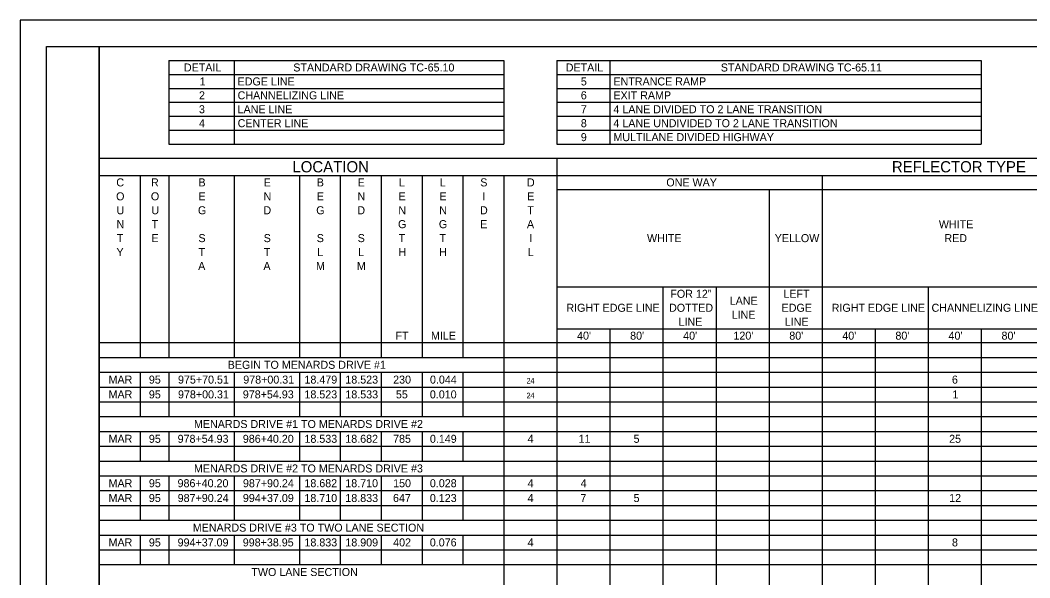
# Model space of a CAD drawing. Extents: x 0 to 34, y 0 to 22.
# Drawn here: x 0 to 19.14, y 11.44 to 22 of the extents above; entities that cross this region are included whole.
import ezdxf

# ---------------------------------------------------------------- set-up
doc = ezdxf.new("R2010")
doc.units = 0
for name, color, linetype in [('SH_Border', 7, 'Continuous'), ('SH_Cut_Line', 7, 'Continuous'), ('SH_Text', 7, 'Continuous')]:
    doc.layers.add(name, color=color, linetype=linetype)

msp = doc.modelspace()

# ---------------------------------------------------------------- linework, layer by layer
at = {"layer": 'SH_Border'}
for points in [[(0.5, 21.5), (1.5, 21.5), (1.5, 0.5), (0.5, 0.5)], [(1.5, 21.5), (33.5, 21.5), (33.5, 0.5), (1.5, 0.5)]]:
    msp.add_lwpolyline(points, close=True, dxfattribs=at)
at = {"layer": 'SH_Cut_Line'}
msp.add_lwpolyline([(0, 0), (34, 0), (34, 22), (0, 22)], close=True, dxfattribs=at)
at = {"layer": 'SH_Text'}
for p, q in [((2.819, 21.237), (9.166, 21.237)), ((2.819, 21.237), (2.819, 19.654)), ((4.055, 21.237), (4.055, 19.654)), ((9.166, 21.237), (9.166, 19.654)), ((10.172, 21.237), (18.217, 21.237)), ((10.172, 21.237), (10.172, 19.654)), ((11.178, 21.237), (11.178, 19.654)), ((18.217, 21.237), (18.217, 19.654)), ((2.819, 20.973), (9.166, 20.973)), ((10.172, 20.973), (18.217, 20.973)), ((2.819, 20.709), (9.166, 20.709)), ((10.172, 20.709), (18.217, 20.709)), ((2.819, 20.446), (9.166, 20.446)), ((10.172, 20.446), (18.217, 20.446)), ((2.819, 20.182), (9.166, 20.182)), ((10.172, 20.182), (18.217, 20.182)), ((2.819, 19.918), (9.166, 19.918)), ((10.172, 19.918), (18.217, 19.918)), ((2.819, 19.654), (9.166, 19.654)), ((10.172, 19.654), (18.217, 19.654)), ((1.5, 19.39), (32, 19.39)), ((1.5, 19.39), (1.5, 0.48)), ((10.172, 19.39), (10.172, 0.761)), ((1.5, 19.061), (32, 19.061)), ((2.275, 19.061), (2.275, 15.615)), ((2.819, 19.061), (2.819, 15.615)), ((4.055, 19.061), (4.055, 15.615)), ((5.292, 19.061), (5.292, 15.615)), ((6.067, 19.061), (6.067, 15.615)), ((6.842, 19.061), (6.842, 15.615)), ((7.616, 19.061), (7.616, 15.615)), ((8.391, 19.061), (8.391, 15.615)), ((9.166, 19.061), (9.166, 0.761)), ((15.2, 19.061), (15.2, 0.761)), ((10.172, 18.797), (25.257, 18.797)), ((14.195, 18.797), (14.195, 0.761)), ((10.172, 16.95), (25.257, 16.95)), ((12.183, 16.95), (12.183, 0.761)), ((13.189, 16.95), (13.189, 0.761)), ((17.212, 16.95), (17.212, 0.761)), ((10.172, 16.159), (26.807, 16.159)), ((11.178, 16.159), (11.178, 0.761)), ((16.206, 16.159), (16.206, 0.761)), ((18.217, 16.159), (18.217, 0.761)), ((1.5, 15.895), (32, 15.895)), ((1.5, 15.615), (32, 15.615)), ((1.5, 15.335), (32, 15.335)), ((2.275, 15.335), (2.275, 14.494)), ((2.819, 15.335), (2.819, 14.494)), ((4.055, 15.335), (4.055, 14.494)), ((5.292, 15.335), (5.292, 14.494)), ((6.067, 15.335), (6.067, 14.494)), ((6.842, 15.335), (6.842, 14.494)), ((7.616, 15.335), (7.616, 14.494)), ((8.391, 15.335), (8.391, 14.494)), ((1.5, 15.054), (32, 15.054)), ((1.5, 14.774), (32, 14.774)), ((1.5, 14.494), (32, 14.494)), ((1.5, 14.214), (32, 14.214)), ((2.275, 14.214), (2.275, 13.653)), ((2.819, 14.214), (2.819, 13.653)), ((4.055, 14.214), (4.055, 13.653)), ((5.292, 14.214), (5.292, 13.653)), ((6.067, 14.214), (6.067, 13.653)), ((6.842, 14.214), (6.842, 13.653)), ((7.616, 14.214), (7.616, 13.653)), ((8.391, 14.214), (8.391, 13.653)), ((1.5, 13.933), (32, 13.933)), ((1.5, 13.653), (32, 13.653)), ((1.5, 13.373), (32, 13.373)), ((2.275, 13.373), (2.275, 12.532)), ((2.819, 13.373), (2.819, 12.532)), ((4.055, 13.373), (4.055, 12.532)), ((5.292, 13.373), (5.292, 12.532)), ((6.067, 13.373), (6.067, 12.532)), ((6.842, 13.373), (6.842, 12.532)), ((7.616, 13.373), (7.616, 12.532)), ((8.391, 13.373), (8.391, 12.532)), ((1.5, 13.093), (32, 13.093)), ((1.5, 12.812), (32, 12.812)), ((1.5, 12.532), (32, 12.532)), ((1.5, 12.252), (32, 12.252)), ((2.275, 12.252), (2.275, 11.691)), ((2.819, 12.252), (2.819, 11.691)), ((4.055, 12.252), (4.055, 11.691)), ((5.292, 12.252), (5.292, 11.691)), ((6.067, 12.252), (6.067, 11.691)), ((6.842, 12.252), (6.842, 11.691)), ((7.616, 12.252), (7.616, 11.691)), ((8.391, 12.252), (8.391, 11.691)), ((1.5, 11.972), (32, 11.972)), ((1.5, 11.691), (32, 11.691))]:
    msp.add_line(p, q, dxfattribs=at)

# ---------------------------------------------------------------- texts
for s, height, p in [('DETAIL', 0.1517, (3.103, 21.029)), ('STANDARD DRAWING TC-65.10', 0.15168, (5.176, 21.029)), ('DETAIL', 0.1517, (10.34, 21.029)), ('STANDARD DRAWING TC-65.11', 0.15168, (13.279, 21.029)), ('1', 0.152, (3.402, 20.765)), ('EDGE LINE', 0.1517, (4.121, 20.765)), ('5', 0.152, (10.626, 20.765)), ('ENTRANCE RAMP', 0.15168, (11.244, 20.765)), ('2', 0.152, (3.389, 20.502)), ('CHANNELIZING LINE', 0.15168, (4.121, 20.502)), ('6', 0.152, (10.626, 20.502)), ('EXIT RAMP', 0.1517, (11.244, 20.502)), ('3', 0.152, (3.388, 20.238)), ('LANE LINE', 0.1517, (4.121, 20.238)), ('7', 0.152, (10.626, 20.238)), ('4 LANE DIVIDED TO 2 LANE TRANSITION', 0.15168, (11.244, 20.238)), ('4', 0.152, (3.389, 19.974)), ('CENTER LINE', 0.15168, (4.121, 19.974)), ('8', 0.152, (10.626, 19.974)), ('4 LANE UNDIVIDED TO 2 LANE TRANSITION', 0.15168, (11.244, 19.974)), ('9', 0.152, (10.626, 19.71)), ('MULTILANE DIVIDED HIGHWAY', 0.15168, (11.244, 19.71)), ('LOCATION', 0.2123, (5.159, 19.119)), ('REFLECTOR TYPE', 0.21235, (16.522, 19.119)), ('C', 0.152, (1.822, 18.853)), ('R', 0.152, (2.479, 18.853)), ('B', 0.152, (3.379, 18.853)), ('E', 0.152, (4.615, 18.853)), ('B', 0.152, (5.621, 18.853)), ('E', 0.152, (6.396, 18.853)), ('L', 0.152, (7.179, 18.853)), ('L', 0.152, (7.954, 18.853)), ('S', 0.152, (8.72, 18.853)), ('D', 0.152, (9.605, 18.853)), ('ONE WAY', 0.1517, (12.247, 18.853)), ('O', 0.152, (1.818, 18.589)), ('O', 0.152, (2.477, 18.589)), ('E', 0.152, (3.379, 18.589)), ('N', 0.152, (4.613, 18.589)), ('E', 0.152, (5.621, 18.589)), ('N', 0.152, (6.393, 18.589)), ('E', 0.152, (7.171, 18.589)), ('E', 0.152, (7.945, 18.589)), ('I', 0.152, (8.761, 18.589)), ('E', 0.152, (9.611, 18.589)), ('U', 0.152, (1.826, 18.325)), ('U', 0.152, (2.486, 18.325)), ('G', 0.152, (3.369, 18.325)), ('D', 0.152, (4.61, 18.325)), ('G', 0.152, (5.611, 18.325)), ('D', 0.152, (6.39, 18.325)), ('N', 0.152, (7.168, 18.325)), ('N', 0.152, (7.943, 18.325)), ('D', 0.152, (8.715, 18.325)), ('T', 0.152, (9.613, 18.325)), ('N', 0.152, (1.826, 18.062)), ('T', 0.152, (2.491, 18.062)), ('G', 0.152, (7.161, 18.062)), ('G', 0.152, (7.936, 18.062)), ('E', 0.152, (8.72, 18.062)), ('A', 0.152, (9.605, 18.062)), ('WHITE', 0.1517, (17.412, 18.062)), ('T', 0.152, (1.831, 17.798)), ('E', 0.152, (2.488, 17.798)), ('S', 0.152, (3.379, 17.798)), ('S', 0.152, (4.615, 17.798)), ('S', 0.152, (5.621, 17.798)), ('S', 0.152, (6.396, 17.798)), ('T', 0.152, (7.173, 17.798)), ('T', 0.152, (7.948, 17.798)), ('I', 0.152, (9.651, 17.798)), ('WHITE', 0.1517, (11.881, 17.798)), ('YELLOW', 0.1517, (14.301, 17.798)), ('RED', 0.1517, (17.518, 17.798)), ('Y', 0.152, (1.825, 17.534)), ('T', 0.152, (3.381, 17.534)), ('T', 0.152, (4.617, 17.534)), ('L', 0.152, (5.63, 17.534)), ('L', 0.152, (6.405, 17.534)), ('H', 0.152, (7.168, 17.534)), ('H', 0.152, (7.943, 17.534)), ('L', 0.152, (9.619, 17.534)), ('A', 0.152, (3.373, 17.27)), ('A', 0.152, (4.61, 17.27)), ('M', 0.152, (5.607, 17.27)), ('M', 0.152, (6.382, 17.27)), ('FOR 12" ', 0.1517, (12.323, 16.744)), ('LEFT ', 0.1517, (14.466, 16.744)), ('LANE  ', 0.1517, (13.448, 16.612)), ('RIGHT EDGE LINE', 0.15168, (10.352, 16.479)), ('DOTTED ', 0.1517, (12.299, 16.479)), ('LINE', 0.1517, (13.485, 16.346)), ('EDGE  ', 0.1517, (14.432, 16.479)), ('RIGHT EDGE LINE', 0.15168, (15.381, 16.479)), ('CHANNELIZING LINE', 0.15168, (17.274, 16.479)), ('LINE', 0.1517, (12.479, 16.213)), ('LINE', 0.1517, (14.491, 16.213)), ('FT', 0.1517, (7.114, 15.951)), ('MILE', 0.1517, (7.786, 15.951)), ("40'", 0.1517, (10.555, 15.951)), ("80'", 0.1517, (11.561, 15.951)), ("40'", 0.1517, (12.566, 15.951)), ("120'", 0.1517, (13.519, 15.951)), ("80'", 0.1517, (14.578, 15.951)), ("40'", 0.1517, (15.583, 15.951)), ("80'", 0.1517, (16.589, 15.951)), ("40'", 0.1517, (17.595, 15.951)), ("80'", 0.1517, (18.6, 15.951)), ('BEGIN TO MENARDS DRIVE #1', 0.15168, (3.933, 15.399)), ('MAR', 0.1517, (1.675, 15.119)), ('95', 0.1517, (2.439, 15.119)), ('975+70.51', 0.1517, (2.991, 15.119)), ('978+00.31', 0.1517, (4.228, 15.119)), ('18.479', 0.1517, (5.388, 15.119)), ('18.523', 0.1517, (6.163, 15.119)), ('230', 0.1517, (7.069, 15.119)), ('0.044', 0.1517, (7.767, 15.119)), ('2', 0.106, (9.596, 15.12)), ('4', 0.106, (9.67, 15.12)), ('6', 0.152, (17.66, 15.119)), ('MAR', 0.1517, (1.675, 14.839)), ('95', 0.1517, (2.439, 14.839)), ('978+00.31', 0.1517, (2.991, 14.839)), ('978+54.93', 0.1517, (4.22, 14.839)), ('18.523', 0.1517, (5.388, 14.839)), ('18.533', 0.1517, (6.163, 14.839)), ('55', 0.1517, (7.121, 14.839)), ('0.010', 0.1517, (7.765, 14.839)), ('2', 0.106, (9.596, 14.84)), ('4', 0.106, (9.67, 14.84)), ('1', 0.152, (17.669, 14.839)), ('MENARDS DRIVE #1 TO MENARDS DRIVE #2', 0.15168, (3.294, 14.278)), ('MAR', 0.1517, (1.675, 13.998)), ('95', 0.1517, (2.439, 13.998)), ('978+54.93', 0.1517, (2.984, 13.998)), ('986+40.20', 0.1517, (4.22, 13.998)), ('18.533', 0.1517, (5.388, 13.998)), ('18.682', 0.1517, (6.162, 13.998)), ('785', 0.1517, (7.068, 13.998)), ('0.149', 0.1517, (7.766, 13.998)), ('4', 0.152, (9.617, 13.998)), ('11', 0.1517, (10.583, 13.998)), ('5', 0.152, (11.626, 13.998)), ('25', 0.1517, (17.607, 13.998)), ('MENARDS DRIVE #2 TO MENARDS DRIVE #3', 0.15168, (3.294, 13.437)), ('MAR', 0.1517, (1.675, 13.157)), ('95', 0.1517, (2.439, 13.157)), ('986+40.20', 0.1517, (2.983, 13.157)), ('987+90.24', 0.1517, (4.222, 13.157)), ('18.682', 0.1517, (5.387, 13.157)), ('18.710', 0.1517, (6.162, 13.157)), ('150', 0.1517, (7.069, 13.157)), ('0.028', 0.1517, (7.765, 13.157)), ('4', 0.152, (9.617, 13.157)), ('4', 0.152, (10.623, 13.157)), ('MAR', 0.1517, (1.675, 12.877)), ('95', 0.1517, (2.439, 12.877)), ('987+90.24', 0.1517, (2.985, 12.877)), ('994+37.09', 0.1517, (4.221, 12.877)), ('18.710', 0.1517, (5.387, 12.877)), ('18.833', 0.1517, (6.163, 12.877)), ('647', 0.1517, (7.066, 12.877)), ('0.123', 0.1517, (7.765, 12.877)), ('4', 0.152, (9.617, 12.877)), ('7', 0.152, (10.618, 12.877)), ('5', 0.152, (11.626, 12.877)), ('12', 0.1517, (17.608, 12.877)), ('MENARDS DRIVE #3 TO TWO LANE SECTION', 0.15168, (3.271, 12.316)), ('MAR', 0.1517, (1.675, 12.036)), ('95', 0.1517, (2.439, 12.036)), ('994+37.09', 0.1517, (2.984, 12.036)), ('998+38.95', 0.1517, (4.219, 12.036)), ('18.833', 0.1517, (5.388, 12.036)), ('18.909', 0.1517, (6.163, 12.036)), ('402', 0.1517, (7.069, 12.036)), ('0.076', 0.1517, (7.764, 12.036)), ('4', 0.152, (9.617, 12.036)), ('8', 0.152, (17.661, 12.036)), ('TWO LANE SECTION', 0.15168, (4.382, 11.475))]:
    msp.add_text(s, height=height, dxfattribs=at).set_placement(p)

doc.saveas('drawing.dxf')
